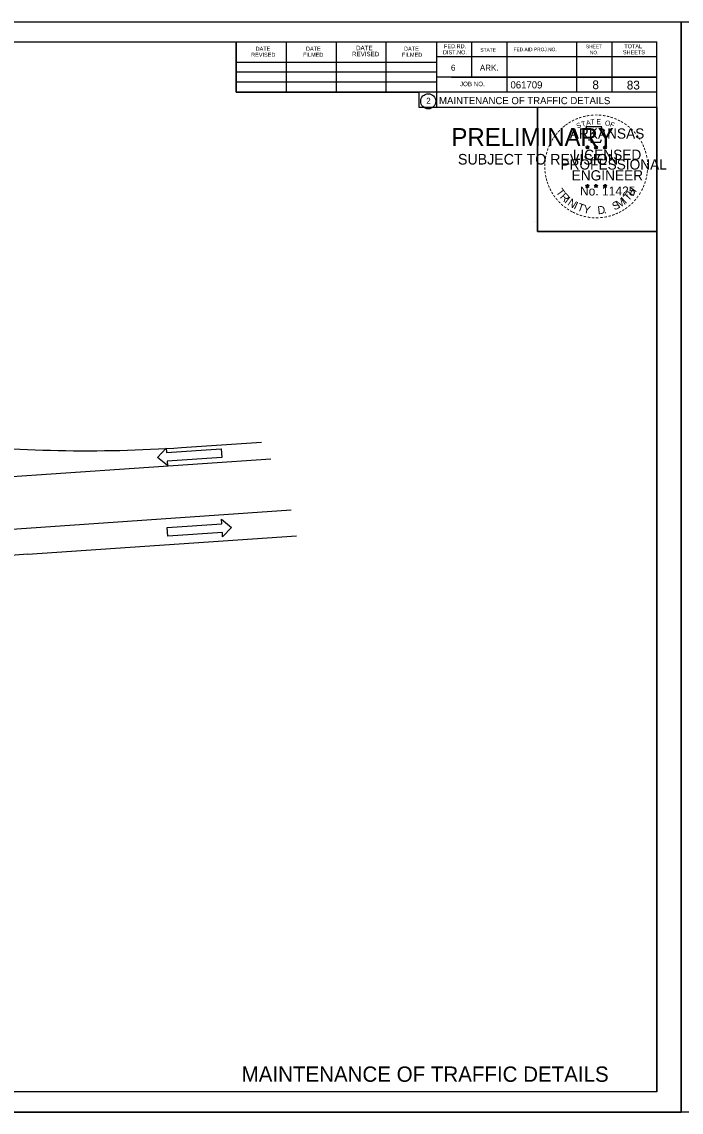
# Model space of a CAD drawing. Extents: x 1397271 to 1411271, y 376395 to 377888.
# Drawn here: x 1401035 to 1401938, y 376395 to 377888 of the extents above; entities that cross this region are included whole.
import ezdxf

# ---------------------------------------------------------------- set-up
doc = ezdxf.new("R2010")
doc.units = 0
for name, color, linetype in [('R_Border', 7, 'Continuous'), ('R_Border PE', 7, 'Continuous'), ('R_Border Prem', 7, 'Continuous'), ('R_Draft', 7, 'Continuous'), ('R_Exist Surface', 7, 'Continuous'), ('R_MOT', 7, 'Continuous'), ('R_No Plot', 7, 'Continuous')]:
    doc.layers.add(name, color=color, linetype=linetype)

msp = doc.modelspace()

# ---------------------------------------------------------------- linework, layer by layer
at = {"layer": 'R_Border'}
for p, q in [((1399691.2, 377860.7), (1401904.5, 377860.7)), ((1401328.6, 377791.6), (1401328.6, 377860.7)), ((1401397.6, 377791.6), (1401397.6, 377859.3)), ((1401466, 377791.6), (1401466, 377859.3)), ((1401533.7, 377791.6), (1401533.7, 377859.3)), ((1401602.7, 377860.7), (1401602.7, 377771.1)), ((1401650.6, 377860.7), (1401650.6, 377812.1)), ((1401699.2, 377860.7), (1401699.2, 377791.6)), ((1401794.3, 377860.7), (1401794.3, 377791.6)), ((1401842.9, 377860.7), (1401842.9, 377791.6)), ((1401904.5, 376422.5), (1401904.5, 377860.7)), ((1401328.6, 377832.6), (1401602.7, 377832.6)), ((1401904.5, 377840.1), (1401602.7, 377840.1)), ((1401904.5, 377840.3), (1401904.5, 377840.3)), ((1401328.6, 377819.6), (1401602.7, 377819.6)), ((1401328.6, 377791.6), (1401328.6, 377806)), ((1401328.6, 377806), (1401602.7, 377806)), ((1401904.5, 377812.1), (1401602.7, 377812.1)), ((1401623.5, 377812.1), (1401904.5, 377812.1)), ((1401904.5, 377791.6), (1401328.6, 377791.6)), ((1401602.7, 377771.1), (1401904.5, 377771.1)), ((1401904.5, 376422.5), (1399691.2, 376422.5))]:
    msp.add_line(p, q, dxfattribs=at)
msp.add_circle((1401591.5, 377779.1), 10.3, dxfattribs=at)
at = {"layer": 'R_Border PE'}
for p, q in [((1401807, 377716.8), (1401809.5, 377716.1)), ((1401807, 377716.8), (1401808.8, 377716.5)), ((1401807, 377716.8), (1401808.7, 377716)), ((1401808, 377714), (1401809.5, 377716.1)), ((1401808, 377714), (1401808.8, 377715.7)), ((1401808, 377714), (1401809.5, 377715.5)), ((1401809.5, 377718.6), (1401809.2, 377716.9)), ((1401809.5, 377716.1), (1401809.5, 377718.6)), ((1401809.5, 377718.6), (1401809.8, 377716.9)), ((1401811.9, 377716.8), (1401809.5, 377716.1)), ((1401811, 377714), (1401809.5, 377716.1)), ((1401811, 377714), (1401809.5, 377715.5)), ((1401811.9, 377716.8), (1401809.9, 377716.5)), ((1401811, 377714), (1401810, 377716)), ((1401811.9, 377716.8), (1401810.5, 377716.1)), ((1401818.7, 377716.8), (1401821.2, 377716.1)), ((1401818.7, 377716.8), (1401820.5, 377716.5)), ((1401818.7, 377716.8), (1401820.4, 377716)), ((1401819.7, 377714), (1401821.2, 377716.1)), ((1401819.7, 377714), (1401820.5, 377715.7)), ((1401819.7, 377714), (1401821.2, 377715.5)), ((1401821.2, 377718.6), (1401820.9, 377716.9)), ((1401821.2, 377716.1), (1401821.2, 377718.6)), ((1401821.2, 377718.6), (1401821.5, 377716.9)), ((1401823.6, 377716.8), (1401821.2, 377716.1)), ((1401822.7, 377714), (1401821.2, 377716.1)), ((1401822.7, 377714), (1401821.2, 377715.5)), ((1401823.6, 377716.8), (1401821.6, 377716.5)), ((1401822.7, 377714), (1401821.7, 377716)), ((1401823.6, 377716.8), (1401822.2, 377716.1)), ((1401831.1, 377716.8), (1401833.5, 377716)), ((1401831.1, 377716.8), (1401832.8, 377716.4)), ((1401831.1, 377716.8), (1401832.7, 377715.9)), ((1401832, 377713.9), (1401833.5, 377716)), ((1401832, 377713.9), (1401832.9, 377715.6)), ((1401832, 377713.9), (1401833.5, 377715.4)), ((1401833.5, 377718.5), (1401833.2, 377716.8)), ((1401833.5, 377716), (1401833.5, 377718.5)), ((1401833.5, 377718.5), (1401833.9, 377716.8)), ((1401835.9, 377716.8), (1401833.5, 377716)), ((1401835, 377713.9), (1401833.5, 377716)), ((1401835, 377713.9), (1401833.5, 377715.4)), ((1401835.9, 377716.8), (1401833.9, 377716.4)), ((1401835, 377713.9), (1401834, 377715.9)), ((1401835.9, 377716.8), (1401834.5, 377716)), ((1401807, 377663.8), (1401809.4, 377663.1)), ((1401807, 377663.8), (1401808.8, 377663.5)), ((1401807, 377663.8), (1401808.7, 377663)), ((1401809.4, 377665.6), (1401809.2, 377663.8)), ((1401809.4, 377663.1), (1401809.4, 377665.6)), ((1401809.4, 377665.6), (1401809.8, 377663.9)), ((1401811.9, 377663.8), (1401809.4, 377663.1)), ((1401811.9, 377663.8), (1401809.9, 377663.5)), ((1401811.9, 377663.8), (1401810.4, 377663.1)), ((1401818.7, 377663.8), (1401821.1, 377663.1)), ((1401818.7, 377663.8), (1401820.5, 377663.5)), ((1401818.7, 377663.8), (1401820.3, 377663)), ((1401821.1, 377665.6), (1401820.8, 377663.8)), ((1401821.1, 377663.1), (1401821.1, 377665.6)), ((1401821.1, 377665.6), (1401821.5, 377663.9)), ((1401823.6, 377663.8), (1401821.1, 377663.1)), ((1401823.6, 377663.8), (1401821.6, 377663.5)), ((1401823.6, 377663.8), (1401822.1, 377663.1)), ((1401831.1, 377663.8), (1401833.5, 377663)), ((1401831.1, 377663.8), (1401832.8, 377663.4)), ((1401831.1, 377663.8), (1401832.7, 377662.9)), ((1401833.5, 377665.5), (1401833.2, 377663.8)), ((1401833.5, 377663), (1401833.5, 377665.5)), ((1401833.5, 377665.5), (1401833.8, 377663.8)), ((1401835.9, 377663.8), (1401833.5, 377663)), ((1401835.9, 377663.8), (1401833.9, 377663.4)), ((1401835.9, 377663.8), (1401834.5, 377663)), ((1401807.9, 377661), (1401809.4, 377663.1)), ((1401807.9, 377661), (1401808.8, 377662.7)), ((1401807.9, 377661), (1401809.4, 377662.5)), ((1401810.9, 377661), (1401809.4, 377663.1)), ((1401810.9, 377661), (1401809.4, 377662.5)), ((1401810.9, 377661), (1401810, 377663)), ((1401819.6, 377661), (1401821.1, 377663.1)), ((1401819.6, 377661), (1401820.5, 377662.7)), ((1401819.6, 377661), (1401821.1, 377662.5)), ((1401822.6, 377661), (1401821.1, 377663.1)), ((1401822.6, 377661), (1401821.1, 377662.5)), ((1401822.6, 377661), (1401821.7, 377663)), ((1401832, 377660.9), (1401833.5, 377663)), ((1401832, 377660.9), (1401832.9, 377662.6)), ((1401832, 377660.9), (1401833.5, 377662.4)), ((1401835, 377660.9), (1401833.5, 377663)), ((1401835, 377660.9), (1401833.5, 377662.4)), ((1401835, 377660.9), (1401834, 377662.9))]:
    msp.add_line(p, q, dxfattribs=at)
for points in [[(1401807.3, 377744), (1401809.2, 377738.2)], [(1401831.9, 377737.5), (1401832.9, 377739.5), (1401828.1, 377739.4), (1401829.1, 377744), (1401807.3, 377744)], [(1401810.8, 377727), (1401810.8, 377726.4), (1401814.7, 377726.3), (1401814.3, 377723), (1401827.4, 377723), (1401828.8, 377726.7)], [(1401809.5, 377718.6), (1401811, 377714), (1401807, 377716.8), (1401811.9, 377716.8), (1401808, 377714), (1401809.5, 377718.6)], [(1401821.2, 377718.6), (1401822.7, 377714), (1401818.7, 377716.8), (1401823.6, 377716.8), (1401819.7, 377714), (1401821.2, 377718.6)], [(1401833.5, 377718.5), (1401835, 377713.9), (1401831.1, 377716.8), (1401835.9, 377716.8), (1401832, 377713.9), (1401833.5, 377718.5)], [(1401809.4, 377665.6), (1401810.9, 377661), (1401807, 377663.8), (1401811.9, 377663.8), (1401807.9, 377661), (1401809.4, 377665.6)], [(1401821.1, 377665.6), (1401822.6, 377661), (1401818.7, 377663.8), (1401823.6, 377663.8), (1401819.6, 377661), (1401821.1, 377665.6)], [(1401833.5, 377665.5), (1401835, 377660.9), (1401831.1, 377663.8), (1401835.9, 377663.8), (1401832, 377660.9), (1401833.5, 377665.5)]]:
    msp.add_lwpolyline(points, dxfattribs=at)
for centre, radius in [((1401809.5, 377716.1), 1.21), ((1401809.5, 377716.1), 1.01), ((1401809.5, 377716.1), 0.81), ((1401809.5, 377716.1), 0.694), ((1401809.5, 377716.1), 0.523), ((1401809.5, 377716.1), 0.347), ((1401809.5, 377716.1), 0.208), ((1401821.2, 377716.1), 1.21), ((1401821.2, 377716.1), 1.01), ((1401821.2, 377716.1), 0.81), ((1401821.2, 377716.1), 0.694), ((1401821.2, 377716.1), 0.523), ((1401821.2, 377716.1), 0.347), ((1401821.2, 377716.1), 0.208), ((1401833.5, 377716), 1.21), ((1401833.5, 377716), 1.01), ((1401833.5, 377716), 0.81), ((1401833.5, 377716), 0.694), ((1401833.5, 377716), 0.523), ((1401833.5, 377716), 0.347), ((1401833.5, 377716), 0.208), ((1401809.4, 377663), 1.21), ((1401809.4, 377663), 1.01), ((1401809.4, 377663), 0.81), ((1401809.4, 377663), 0.694), ((1401821.1, 377663), 1.21), ((1401821.1, 377663), 1.01), ((1401821.1, 377663), 0.81), ((1401821.1, 377663), 0.694), ((1401833.5, 377663), 1.21), ((1401833.5, 377663), 1.01), ((1401833.5, 377663), 0.81), ((1401833.5, 377663), 0.694), ((1401809.4, 377663), 0.523), ((1401809.4, 377663), 0.347), ((1401809.4, 377663), 0.208), ((1401821.1, 377663), 0.523), ((1401821.1, 377663), 0.347), ((1401821.1, 377663), 0.208), ((1401833.5, 377663), 0.523), ((1401833.5, 377663), 0.347), ((1401833.5, 377663), 0.208)]:
    msp.add_circle(centre, radius, dxfattribs=at)
at = {"layer": 'R_Exist Surface'}
for p, q in [((1401253.7, 377304.9), (1401363.1, 377312.4)), ((1400062.7, 377199.7), (1401376.1, 377289.5)), ((1400068.1, 377128.3), (1401404.1, 377219.4)), ((1401042.8, 377158.7), (1401411.1, 377183.8))]:
    msp.add_line(p, q, dxfattribs=at)
for centre, start, end in [((1401124.3, 379202.9), 263.7335, 273.9), ((1401172.3, 375260.7), 93.9033, 109.9033)]:
    msp.add_arc(centre, 1902.4, start, end, dxfattribs=at)
at = {"layer": 'R_MOT'}
for p, q in [((1401220.7, 377291.2), (1401233, 377304.1)), ((1401234.7, 377280.1), (1401220.7, 377291.2)), ((1401233, 377304.1), (1401233.4, 377298.1)), ((1401233.4, 377298.1), (1401308.2, 377303.2)), ((1401309, 377291.2), (1401234.2, 377286.1)), ((1401308.2, 377303.2), (1401309, 377291.2)), ((1401234.2, 377286.1), (1401234.7, 377280.1)), ((1401308.9, 377200.6), (1401308.5, 377206.6)), ((1401308.5, 377206.6), (1401322.4, 377195.5)), ((1401234.1, 377195.5), (1401308.9, 377200.6)), ((1401234.9, 377183.5), (1401234.1, 377195.5)), ((1401309.7, 377188.6), (1401234.9, 377183.5)), ((1401310.1, 377182.7), (1401309.7, 377188.6)), ((1401322.4, 377195.5), (1401310.1, 377182.7))]:
    msp.add_line(p, q, dxfattribs=at)
at = {"layer": 'R_No Plot'}
for p, q in [((1399604.3, 377888), (1401937.7, 377888)), ((1401736.7, 377613.9), (1401736.7, 377613.9)), ((1399604.3, 376394.6), (1401937.7, 376394.6))]:
    msp.add_line(p, q, dxfattribs=at)
for points in [[(1399604.3, 377888), (1401937.7, 377888), (1401937.7, 376394.6), (1399604.3, 376394.6)], [(1401937.7, 377888), (1404271.1, 377888), (1404271.1, 376394.6), (1401937.7, 376394.6)], [(1401328.6, 377860.7), (1401328.6, 377791.6), (1401578.8, 377791.6), (1401578.8, 377771.1), (1401741.2, 377771.1), (1401741.2, 377600.8), (1401904.5, 377600.8), (1401904.5, 376422.5), (1399691.2, 376422.5), (1399691.2, 377860.7)], [(1401741.2, 377771.3), (1401904.5, 377771.3), (1401904.5, 377600.8), (1401741.2, 377600.8)]]:
    msp.add_lwpolyline(points, close=True, dxfattribs=at)

# ---------------------------------------------------------------- texts
at = {"layer": 'R_Border'}
for s, height, p in [('REVISED', 5.47, (1401349.1, 377840.1)), ('DATE', 5.47, (1401355.2, 377848.4)), ('FILMED', 5.47, (1401420.2, 377840.1)), ('DATE', 5.47, (1401424.2, 377848.4)), ('REVISED', 6.15, (1401487.2, 377840.8)), ('DATE', 6.15, (1401492.7, 377849.1)), ('FILMED', 5.47, (1401555.6, 377840.1)), ('DATE', 5.47, (1401558.4, 377848.4)), ('DIST.NO.', 5.47, (1401611.7, 377843.5)), ('FED.RD.', 5.47, (1401613.1, 377851.8)), ('STATE', 4.79, (1401662.9, 377847)), ('FED.AID PROJ.NO.', 4.788, (1401708.2, 377847.7)), ('SHEET', 4.79, (1401807.3, 377851.8)), ('NO.', 4.79, (1401812.8, 377843.5)), ('SHEETS', 5.47, (1401858, 377843.5)), ('TOTAL', 5.47, (1401859.9, 377851.8)), ('6', 8.21, (1401622.6, 377821)), ('ARK.', 8.21, (1401662.2, 377821)), ('JOB NO.', 6.15, (1401634.9, 377799.8)), ('061709', 9.8, (1401704.1, 377796.7)), ('2', 8.21, (1401588.8, 377775.7)), ('MAINTENANCE OF TRAFFIC DETAILS', 9.8, (1401606.3, 377775.2)), ('MAINTENANCE OF TRAFFIC DETAILS', 21, (1401336.1, 376436.2))]:
    msp.add_text(s, height=height, dxfattribs=at).set_placement(p)
at = {"layer": 'R_Border PE'}
for s, height, rotation, p in [('-', 11.2, 28.7918, (1401789.7, 377747.8)), ('-', 11.2, 24.3072, (1401794.1, 377750)), ('-', 11.2, 19.1761, (1401798.6, 377751.9)), ('-', 11.2, 13.6302, (1401803.8, 377753.6)), ('A', 7, 11.2132, (1401808, 377745.8)), ('-', 11.2, 10.2193, (1401808.5, 377754.7)), ('T', 7, 6.0228, (1401813.9, 377747)), ('-', 11.2, 5.8968, (1401813.7, 377755.5)), ('-', 11.2, 0.1862, (1401819.1, 377756)), ('E', 7, 0.8323, (1401821.7, 377747.7)), ('-', 11.2, 357.743, (1401824.1, 377755.9)), ('-', 11.2, 352.1617, (1401829.3, 377755.5)), ('-', 11.2, 347.2049, (1401834.4, 377754.7)), ('-', 11.2, 342.3362, (1401838.8, 377753.6)), ('-', 11.2, 337.8551, (1401843.9, 377752)), ('-', 11.2, 334.1211, (1401848.4, 377750.1)), ('-', 11.2, 48.4231, (1401772, 377733.5)), ('-', 11.2, 42.9622, (1401775.1, 377736.9)), ('-', 11.2, 38.9507, (1401778.1, 377739.8)), ('-', 11.2, 36.2317, (1401781.5, 377742.4)), ('-', 11.2, 34.0636, (1401785.5, 377745.2)), ('S', 7, 21.594, (1401795.8, 377741.7)), ('T', 7, 16.4036, (1401802.2, 377744.1)), ('O', 7, 350.4515, (1401832.9, 377746.3)), ('F', 7, 340.0707, (1401839.6, 377744.7)), ('-', 11.2, 329.6409, (1401852.4, 377748.2)), ('-', 11.2, 325.8627, (1401856.9, 377745.6)), ('-', 11.2, 320.5297, (1401861.2, 377742.7)), ('-', 11.2, 315.5786, (1401865.4, 377739.2)), ('-', 11.2, 62.8713, (1401761.8, 377718.1)), ('-', 11.2, 58.0706, (1401764, 377722.4)), ('-', 11.2, 54.2325, (1401766.2, 377726.1)), ('-', 11.2, 50.6142, (1401769.1, 377730.1)), ('-', 11.2, 309.8797, (1401869.4, 377735.4)), ('-', 11.2, 306.6522, (1401873, 377731.2)), ('-', 9.8, 303.6753, (1401876.4, 377727.2)), ('-', 11.2, 299.6684, (1401878.7, 377723)), ('-', 11.2, 75.461, (1401757.1, 377704.5)), ('-', 11.2, 72.3945, (1401758.4, 377709.5)), ('-', 11.2, 67.7743, (1401760, 377713.9)), ('-', 11.2, 294.6628, (1401880.9, 377718.7)), ('-', 11.2, 290.5728, (1401882.7, 377714.6)), ('-', 11.2, 285.1233, (1401884.4, 377710.6)), ('-', 11.2, 89.0622, (1401755.4, 377689.7)), ('-', 11.2, 85.1863, (1401755.6, 377694.6)), ('-', 11.2, 81.2013, (1401756.1, 377699.5)), ('-', 11.2, 280.5493, (1401885.8, 377705.4)), ('-', 11.2, 276.5962, (1401886.9, 377700)), ('-', 11.2, 274.3301, (1401887.3, 377694.9)), ('-', 11.2, 94.1959, (1401755.7, 377684.7)), ('-', 11.2, 98.9479, (1401756.2, 377680)), ('-', 11.2, 260.9953, (1401886.9, 377681.3)), ('-', 11.2, 263.5172, (1401887.4, 377685.9)), ('-', 11.2, 269.9407, (1401887.6, 377690.5)), ('-', 11.2, 101.7149, (1401757.1, 377674.9)), ('-', 11.2, 105.4578, (1401758.3, 377670.7)), ('-', 11.2, 109.0874, (1401759.8, 377666.3)), ('-', 11.2, 114.0643, (1401761.5, 377662.1)), ('-', 11.2, 247.8887, (1401883.3, 377666.8)), ('-', 11.2, 252.8681, (1401884.9, 377671.5)), ('-', 11.2, 255.7626, (1401886.2, 377676.5)), ('-', 11.2, 115.7289, (1401763.7, 377657.8)), ('-', 11.2, 120.4471, (1401766.2, 377653.7)), ('-', 11.2, 125.8934, (1401769, 377649.7)), ('T', 10.8, 306.0406, (1401765.8, 377654.9)), ('R', 10.8, 314.005, (1401771.1, 377647.6)), ('I', 10.8, 321.9694, (1401777.4, 377641.1)), ('T', 10.8, 46.6444, (1401865.4, 377641.6)), ('H', 10.8, 54.6088, (1401871.6, 377648.2)), ('-', 11.2, 233.8452, (1401875.9, 377652.5)), ('-', 11.2, 239.0712, (1401878.8, 377657.1)), ('-', 11.2, 244.6197, (1401881.5, 377662.4)), ('-', 11.2, 130.7181, (1401772.2, 377645.9)), ('-', 11.2, 134.2238, (1401775.8, 377642.1)), ('-', 11.2, 138.9338, (1401779.5, 377638.8)), ('-', 11.2, 144.6463, (1401783.4, 377636)), ('N', 10.8, 326.5002, (1401781.4, 377637.8)), ('I', 10.8, 335.3603, (1401789.8, 377632.3)), ('T', 10.8, 339.8912, (1401794.5, 377630)), ('Y', 10.8, 347.8556, (1401803, 377626.8)), ('D', 10.8, 6.3969, (1401823.9, 377624.3)), ('S', 10.8, 26.9312, (1401846.6, 377629.5)), ('M', 10.8, 32.6563, (1401852.5, 377632.3)), ('I', 10.8, 42.1136, (1401861.4, 377638.2)), ('-', 11.2, 215.7363, (1401862.1, 377637.8)), ('-', 11.2, 221.0851, (1401865.9, 377641.1)), ('-', 11.2, 225.7653, (1401869.6, 377644.6)), ('-', 11.2, 231.2538, (1401872.9, 377648.6)), ('-', 11.2, 148.0898, (1401787.3, 377633.4)), ('-', 11.2, 151.5704, (1401791.4, 377631.1)), ('-', 11.2, 154.6002, (1401795, 377629.4)), ('-', 11.2, 158.5612, (1401799.4, 377627.6)), ('-', 11.2, 162.7983, (1401804.2, 377626.1)), ('-', 11.2, 167.5555, (1401809.2, 377625)), ('-', 11.2, 173.1155, (1401814.6, 377624.2)), ('-', 11.2, 176.5183, (1401819.9, 377623.8)), ('-', 11.2, 181.5918, (1401825.1, 377623.9)), ('-', 11.2, 185.8167, (1401830.7, 377624.5)), ('-', 11.2, 191.2858, (1401835.9, 377625.4)), ('.', 10.8, 13.7642, (1401832.2, 377625.2)), ('-', 11.2, 195.4743, (1401841, 377626.8)), ('-', 11.2, 200.7184, (1401845.7, 377628.5)), ('-', 11.2, 204.2516, (1401850.1, 377630.4)), ('-', 11.2, 207.3568, (1401854.4, 377632.6)), ('-', 11.2, 212.2491, (1401858.3, 377635.1))]:
    msp.add_text(s, height=height, rotation=rotation, dxfattribs=at).set_placement(p)
for s, height, p in [('ARKANSAS', 14, (1401785.3, 377728)), ('LICENSED', 14, (1401789.5, 377698.9)), ('DWB', 0.07, (1401809.4, 377716)), ('DWB', 0.07, (1401821.1, 377716)), ('DWB', 0.07, (1401833.4, 377716)), ('PROFESSIONAL', 14, (1401772.5, 377685.6)), ('ENGINEER', 14, (1401787.8, 377670.7)), ('No. 11425', 12.3, (1401799.2, 377650.1)), ('DWB', 0.07, (1401809.4, 377663)), ('DWB', 0.07, (1401821, 377663)), ('DWB', 0.07, (1401833.4, 377662.9))]:
    msp.add_text(s, height=height, dxfattribs=at).set_placement(p)
at = {"layer": 'R_Border Prem'}
for s, height, p in [('PRELIMINARY', 24.5, (1401623.3, 377717.9)), ('DWB', 0.07, (1401624.8, 377730.9)), ('SUBJECT TO REVISION', 14.526, (1401632.2, 377692.5))]:
    msp.add_text(s, height=height, dxfattribs=at).set_placement(p)
at = {"layer": 'R_Draft'}
for s, p in [('8', (1401816.2, 377795.7)), ('83', (1401863.3, 377795.3))]:
    msp.add_text(s, height=12, rotation=360, dxfattribs=at).set_placement(p)

doc.saveas('drawing.dxf')
